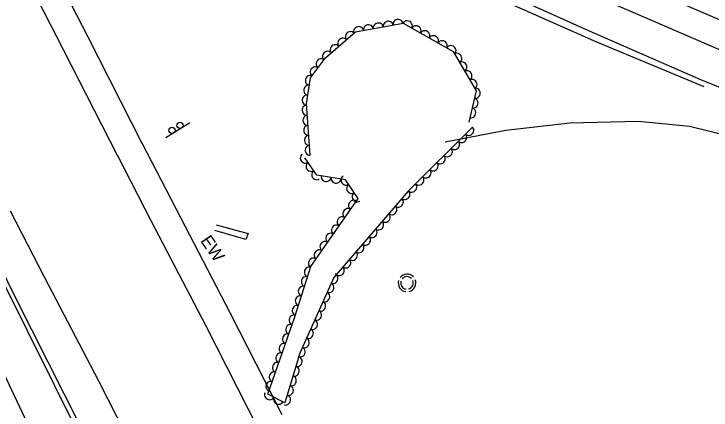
# Model space of a CAD drawing. Extents: x 1746719 to 1766531, y 631721 to 662391.
# Drawn here: x 1755247.8 to 1755525.4, y 647710.8 to 647868.4 of the extents above; entities that cross this region are included whole.
import ezdxf

# ---------------------------------------------------------------- set-up
doc = ezdxf.new("R2010")
doc.units = 0
for name, color, linetype in [('SURVEY - AERIAL SURVEY - Photo Control - Points - Elevations', 7, 'Continuous'), ('SURVEY - AERIAL SURVEY - Photo Control - Points - Numbers', 7, 'Continuous'), ('SURVEY - AERIAL SURVEY - Photo Control with Text', 7, 'Continuous'), ('SURVEY - CENTERLINE - Existing Roads - Development', 7, 'Continuous'), ('SURVEY - CENTERLINE - Existing Roads Text', 7, 'Continuous'), ('SURVEY - CENTERLINE - Preliminary - Development', 7, 'Continuous'), ('SURVEY - CONTROL - Grid', 7, 'Continuous')]:
    doc.layers.add(name, color=color, linetype=linetype)

msp = doc.modelspace()

# ---------------------------------------------------------------- linework, layer by layer
at = {"layer": 'SURVEY - AERIAL SURVEY - Photo Control - Points - Elevations'}
for points in [[(1755162.63, 648108.57), (1755186.38, 648078.54), (1755213.88, 648048.33), (1755235.91, 648026.59), (1755264.37, 648002.95), (1755292.76, 647981.76), (1755325.92, 647960.48), (1755367.07, 647938.99), (1755409.68, 647918.8), (1755458.87, 647896.44), (1755506.36, 647875.88), (1755550.22, 647856.88)], [(1755154, 648101.74), (1755177.99, 648071.41), (1755205.94, 648040.71), (1755228.51, 648018.43), (1755257.56, 647994.31), (1755286.49, 647972.71), (1755320.39, 647950.96), (1755362.17, 647929.15), (1755405.05, 647908.82), (1755454.41, 647886.38), (1755501.99, 647865.79), (1755545.85, 647846.79)], [(1755289.08, 647811.89), (1755267.5, 647854.18), (1755238.58, 647910.31), (1755205.95, 647973.71), (1755178.75, 648026.22), (1755153.52, 648075.57), (1755145.13, 648092.61)], [(1755521.37, 647842.24), (1755476.95, 647861.52), (1755416.33, 647888.92), (1755376.39, 647906.97), (1755328.51, 647930.92), (1755302.56, 647945.89), (1755268.89, 647968.38), (1755239.66, 647991.25), (1755212.62, 648015.53), (1755188.3, 648040.38), (1755165.7, 648065.52), (1755145.13, 648092.61)], [(1755298.87, 647816.89), (1755277.28, 647859.2), (1755248.36, 647915.35), (1755215.73, 647978.76), (1755184.78, 648038.49)], [(1755184.88, 648038.39), (1755217.31, 648006.82), (1755242.53, 647984.32), (1755269.2, 647963.56), (1755298.39, 647944.57), (1755330.97, 647926.25), (1755365.16, 647909), (1755400.21, 647892.14), (1755440.79, 647874.67), (1755479.75, 647857.38), (1755522.46, 647839.58)], [(1755840.58, 647610.43), (1755842.28, 647619.97), (1755840.2, 647628.96), (1755836.03, 647639.29), (1755823.78, 647657.34), (1755815.52, 647669.03), (1755803.22, 647684.9), (1755792.97, 647696.45), (1755779.87, 647709.45), (1755761.11, 647725.73), (1755743.38, 647739.86), (1755723.18, 647754.54), (1755706.04, 647766), (1755691.84, 647774.99), (1755672.19, 647783.03), (1755638.35, 647795.66), (1755603.54, 647809.02), (1755565.61, 647824.24), (1755521.37, 647842.24)], [(1755298.74, 647817.14), (1755312.22, 647791.05), (1755333.93, 647749.42), (1755354.49, 647709.05)], [(1755288.97, 647812.1), (1755302.46, 647785.98), (1755324.15, 647744.38), (1755345.02, 647703.4)], [(1755246.32, 647790.07), (1755259.85, 647763.87), (1755281.49, 647722.39), (1755303.35, 647679.45), (1755327.24, 647633.35), (1755350.61, 647588.44), (1755379.31, 647534.22)], [(1755216.81, 647783.61), (1755240.43, 647732.15), (1755263.46, 647683.37), (1755284.21, 647640.6), (1755306.93, 647594.62), (1755324.71, 647559.76), (1755344.14, 647522.71), (1755359.78, 647492.78), (1755374.92, 647465.68)]]:
    msp.add_lwpolyline(points, dxfattribs=at)
at = {"layer": 'SURVEY - AERIAL SURVEY - Photo Control - Points - Numbers'}
for points in [[(1755650.91, 647754.57), (1755637.11, 647767.24), (1755622.28, 647778.82), (1755603.14, 647789.82), (1755588.63, 647799.38), (1755563.09, 647810.15), (1755541.05, 647817.62), (1755516.78, 647823.63), (1755496.46, 647825.57), (1755469.17, 647824.96), (1755443.61, 647822.06), (1755419.56, 647817.41)], [(1755230.73, 647786.86), (1755252.84, 647742.78), (1755274.73, 647699.01), (1755301.72, 647645.7), (1755326.5, 647598.52), (1755351.66, 647550.12), (1755372.35, 647510.46)], [(1755232.79, 647787.12), (1755248.28, 647755.7), (1755274.16, 647704.56), (1755294.2, 647664.62), (1755315.17, 647623.99), (1755333.15, 647588.96), (1755354.63, 647548.15), (1755373.37, 647512.79)]]:
    msp.add_lwpolyline(points, dxfattribs=at)
at = {"layer": 'SURVEY - AERIAL SURVEY - Photo Control with Text'}
for points in [[(1755365.78, 647812.16), (1755364.23, 647832.71), (1755365.85, 647843.04), (1755371.82, 647850.99), (1755383.8, 647861.25), (1755402.77, 647864.71), (1755422.66, 647853.43), (1755431.8, 647837.81), (1755428.95, 647825.34)], [(1755430.38, 647823.42), (1755404.7, 647797.9), (1755375.1, 647763.58), (1755361.65, 647733.51), (1755355.7, 647713.75), (1755348.91, 647717.11), (1755359.65, 647747.88), (1755366.02, 647767.92), (1755384.82, 647795.04), (1755379.86, 647802.36), (1755368.4, 647804.21), (1755363.65, 647811.13)]]:
    msp.add_lwpolyline(points, dxfattribs=at)
for centre, major_axis in [((1755396.81, 647863.62), (1.97, 0.36)), ((1755400.74, 647864.34), (1.97, 0.36)), ((1755404.46, 647863.75), (1.74, -0.99)), ((1755385, 647861.47), (1.97, 0.36)), ((1755388.94, 647862.19), (1.97, 0.36)), ((1755392.87, 647862.91), (1.97, 0.36)), ((1755407.94, 647861.78), (1.74, -0.99)), ((1755381.69, 647859.45), (1.52, 1.3)), ((1755411.41, 647859.81), (1.74, -0.99)), ((1755414.89, 647857.83), (1.74, -0.99)), ((1755378.65, 647856.84), (1.52, 1.3)), ((1755418.37, 647855.86), (1.74, -0.99)), ((1755375.61, 647854.24), (1.52, 1.3)), ((1755421.85, 647853.89), (1.74, -0.99)), ((1755372.58, 647851.64), (1.52, 1.3)), ((1755424.21, 647850.78), (1.01, -1.73)), ((1755370.02, 647848.59), (1.2, 1.6)), ((1755426.23, 647847.33), (1.01, -1.73)), ((1755367.62, 647845.39), (1.2, 1.6)), ((1755428.25, 647843.87), (1.01, -1.73)), ((1755365.69, 647841.99), (0.31, 1.98)), ((1755430.27, 647840.42), (1.01, -1.73)), ((1755365.07, 647838.04), (0.31, 1.98)), ((1755431.59, 647836.86), (-0.45, -1.95)), ((1755364.45, 647834.08), (0.31, 1.98)), ((1755430.69, 647832.96), (-0.45, -1.95)), ((1755364.43, 647830.11), (-0.15, 1.99)), ((1755429.8, 647829.06), (-0.45, -1.95)), ((1755364.73, 647826.12), (-0.15, 1.99)), ((1755365.03, 647822.13), (-0.15, 1.99)), ((1755428.96, 647822.01), (-1.42, -1.41)), ((1755365.33, 647818.14), (-0.15, 1.99)), ((1755426.12, 647819.19), (-1.42, -1.41)), ((1755365.63, 647814.15), (-0.15, 1.99)), ((1755423.29, 647816.37), (-1.42, -1.41)), ((1755420.45, 647813.55), (-1.42, -1.41)), ((1755363.72, 647811.02), (-1.13, 1.65)), ((1755417.61, 647810.73), (-1.42, -1.41)), ((1755365.99, 647807.72), (-1.13, 1.65)), ((1755414.77, 647807.91), (-1.42, -1.41)), ((1755368.25, 647804.43), (-1.13, 1.65)), ((1755411.94, 647805.09), (-1.42, -1.41)), ((1755372.09, 647803.62), (-1.97, 0.32)), ((1755376.04, 647802.98), (-1.97, 0.32)), ((1755379.93, 647802.25), (-1.12, 1.66)), ((1755409.1, 647802.27), (-1.42, -1.41)), ((1755382.18, 647798.94), (-1.12, 1.66)), ((1755406.26, 647799.45), (-1.42, -1.41)), ((1755384.42, 647795.63), (-1.12, 1.66)), ((1755403.53, 647796.54), (-1.31, -1.51)), ((1755382.94, 647792.34), (1.14, 1.64)), ((1755400.91, 647793.51), (-1.31, -1.51)), ((1755380.66, 647789.05), (1.14, 1.64)), ((1755398.3, 647790.48), (-1.31, -1.51)), ((1755378.38, 647785.76), (1.14, 1.64)), ((1755395.69, 647787.45), (-1.31, -1.51)), ((1755393.07, 647784.42), (-1.31, -1.51)), ((1755376.11, 647782.47), (1.14, 1.64)), ((1755390.46, 647781.39), (-1.31, -1.51)), ((1755373.83, 647779.19), (1.14, 1.64)), ((1755387.85, 647778.37), (-1.31, -1.51)), ((1755371.55, 647775.9), (1.14, 1.64)), ((1755385.24, 647775.34), (-1.31, -1.51)), ((1755369.27, 647772.61), (1.14, 1.64)), ((1755366.99, 647769.32), (1.14, 1.64)), ((1755382.62, 647772.31), (-1.31, -1.51)), ((1755380.01, 647769.28), (-1.31, -1.51)), ((1755365.32, 647765.73), (0.61, 1.91)), ((1755377.4, 647766.25), (-1.31, -1.51)), ((1755364.11, 647761.92), (0.61, 1.91)), ((1755374.9, 647763.15), (-0.82, -1.83)), ((1755362.9, 647758.11), (0.61, 1.91)), ((1755373.27, 647759.5), (-0.82, -1.83)), ((1755371.64, 647755.84), (-0.82, -1.83)), ((1755361.69, 647754.3), (0.61, 1.91)), ((1755360.48, 647750.49), (0.61, 1.91)), ((1755370, 647752.19), (-0.82, -1.83)), ((1755359.23, 647746.68), (0.66, 1.89)), ((1755368.37, 647748.54), (-0.82, -1.83)), ((1755366.74, 647744.89), (-0.82, -1.83)), ((1755357.92, 647742.91), (0.66, 1.89)), ((1755356.6, 647739.13), (0.66, 1.89)), ((1755365.11, 647741.24), (-0.82, -1.83)), ((1755363.47, 647737.59), (-0.82, -1.83)), ((1755355.28, 647735.35), (0.66, 1.89)), ((1755361.84, 647733.93), (-0.82, -1.83)), ((1755353.96, 647731.58), (0.66, 1.89)), ((1755352.64, 647727.8), (0.66, 1.89)), ((1755360.63, 647730.13), (-0.58, -1.92)), ((1755359.48, 647726.3), (-0.58, -1.92)), ((1755351.33, 647724.03), (0.66, 1.89)), ((1755358.32, 647722.47), (-0.58, -1.92)), ((1755350.01, 647720.25), (0.66, 1.89)), ((1755357.17, 647718.64), (-0.58, -1.92)), ((1755349.52, 647716.81), (-1.79, 0.89)), ((1755353.1, 647715.03), (-1.79, 0.89)), ((1755356.02, 647714.81), (-0.58, -1.92))]:
    msp.add_ellipse(centre, major_axis=major_axis, ratio=0.940188, start_param=0, end_param=3.141593, dxfattribs=at)
at = {"layer": 'SURVEY - CENTERLINE - Existing Roads - Development'}
for radius, start, end in [(3.5, 43.4555, 140.7502), (2.5, 44.2579, 140.6961), (3.5, 164.8923, 261.6853), (2.5, 164.8102, 261.6448), (2.5, 285.0465, 21.5915), (3.5, 285.0492, 21.4955)]:
    msp.add_arc((1755404.3, 647761.4), radius, start, end, dxfattribs=at)
at = {"layer": 'SURVEY - CENTERLINE - Existing Roads Text'}
msp.add_lwpolyline([(1755328.34, 647784.56), (1755341.1, 647781.05), (1755340.14, 647778.62), (1755327.72, 647782.2)], dxfattribs=at)
at = {"layer": 'SURVEY - CONTROL - Grid'}
msp.add_line((1755317.78, 647825.11), (1755308.31, 647819.14), dxfattribs=at)
for centre in [(1755313.9, 647824.11), (1755310.72, 647822.11)]:
    msp.add_circle(centre, 1.25, dxfattribs=at)

# ---------------------------------------------------------------- texts
at = {"layer": 'SURVEY - CENTERLINE - Preliminary - Development'}
msp.add_text('EW', height=5, rotation=304.4999, dxfattribs=at).set_placement((1755321.83, 647778.17))

doc.saveas('drawing.dxf')
